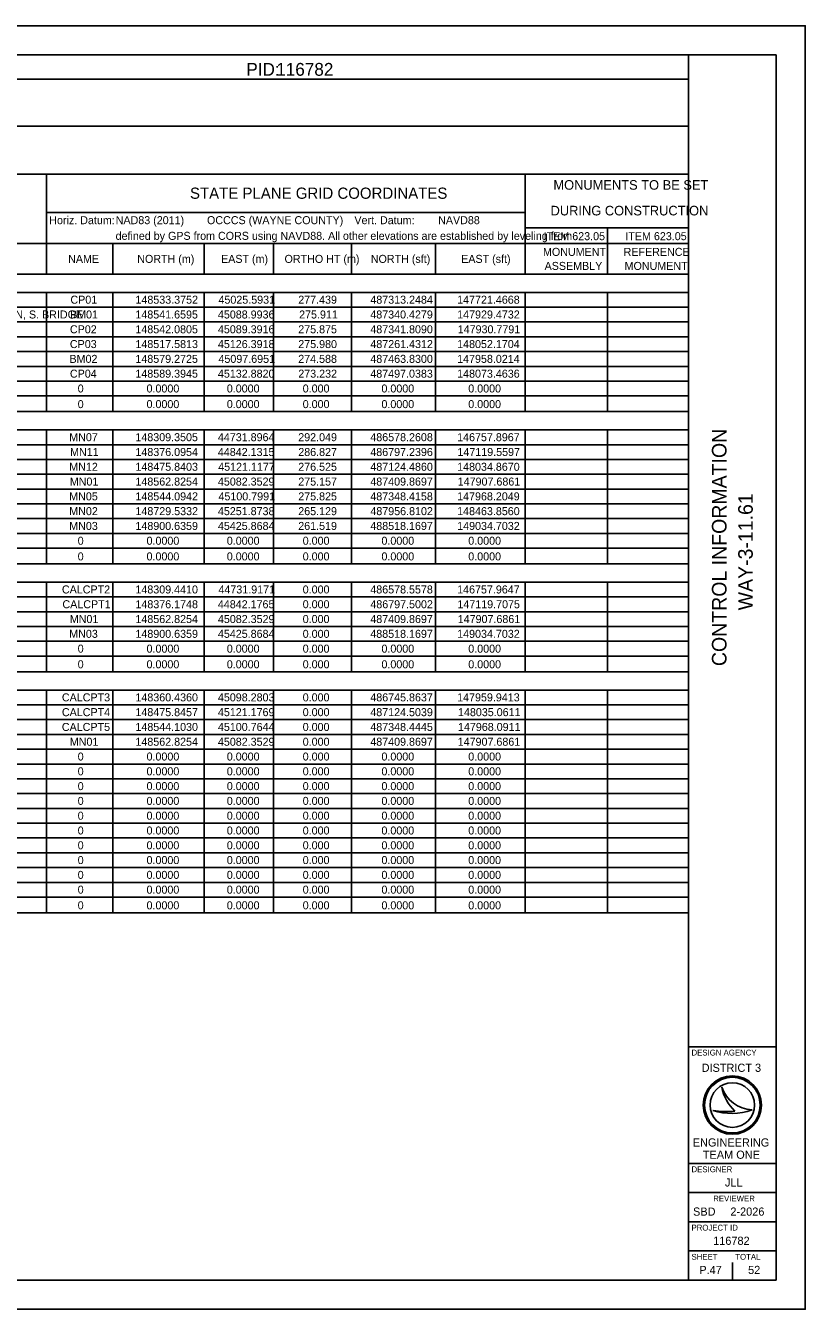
# Model space of a CAD drawing. Extents: x 0 to 680, y 0 to 440.
# Drawn here: x 412.9 to 680, y 0 to 440 of the extents above; entities that cross this region are included whole.
import ezdxf

# ---------------------------------------------------------------- set-up
doc = ezdxf.new("R2010")
doc.units = 0
for name, color, linetype in [('SH_Border', 7, 'Continuous'), ('SH_Cut_Line', 7, 'Continuous'), ('SH_Data', 7, 'Continuous')]:
    doc.layers.add(name, color=color, linetype=linetype)

msp = doc.modelspace()

# ---------------------------------------------------------------- linework, layer by layer
at = {"layer": 'SH_Border'}
for p, q in [((640, 10), (640, 430)), ((640, 90), (670, 90)), ((640, 50), (670, 50)), ((640, 40), (670, 40)), ((640, 30), (670, 30)), ((640, 20), (670, 20))]:
    msp.add_line(p, q, dxfattribs=at)
msp.add_lwpolyline([(30, 430), (670, 430), (670, 10), (30, 10)], close=True, dxfattribs=at)
at = {"layer": 'SH_Cut_Line'}
msp.add_lwpolyline([(0, 0), (680, 0), (680, 440), (0, 440)], close=True, dxfattribs=at)
at = {"layer": 'SH_Data'}
for p, q in [((30, 421.65), (640, 421.65)), ((640, 421.65), (640, 389.14)), ((259.49, 405.54), (640, 405.54)), ((259.49, 389.14), (640, 389.14)), ((419.99, 389.14), (419.99, 354.84)), ((584.05, 389.14), (584.05, 354.84)), ((640, 389.14), (640, 135.91)), ((419.99, 376.01), (584.05, 376.01)), ((584.05, 370.65), (640, 370.65)), ((612.26, 370.65), (612.26, 354.84)), ((30, 365.28), (640, 365.28)), ((442.75, 365.28), (442.75, 354.84)), ((474.05, 365.28), (474.05, 354.84)), ((497.75, 365.28), (497.75, 354.84)), ((524.54, 365.28), (524.54, 354.84)), ((553.23, 365.28), (553.23, 354.84)), ((30, 354.84), (640, 354.84)), ((30, 348.57), (640, 348.57)), ((419.99, 348.57), (419.99, 307.71)), ((442.75, 348.57), (442.75, 307.71)), ((474.05, 348.57), (474.05, 307.71)), ((497.75, 348.57), (497.75, 307.71)), ((524.54, 348.57), (524.54, 307.71)), ((553.23, 348.57), (553.23, 307.71)), ((584.05, 348.57), (584.05, 307.71)), ((612.26, 348.57), (612.26, 307.71)), ((30, 343.5), (640, 343.5)), ((30, 338.43), (640, 338.43)), ((30, 333.36), (640, 333.36)), ((30, 328.29), (640, 328.29)), ((30, 323.22), (640, 323.22)), ((30, 318.15), (640, 318.15)), ((30, 313.08), (640, 313.08)), ((30, 307.71), (640, 307.71)), ((30, 301.45), (640, 301.45)), ((419.99, 301.45), (419.99, 255.52)), ((442.75, 301.45), (442.75, 255.52)), ((474.05, 301.45), (474.05, 255.52)), ((497.75, 301.45), (497.75, 255.52)), ((524.54, 301.45), (524.54, 255.52)), ((553.23, 301.45), (553.23, 255.52)), ((584.05, 301.45), (584.05, 255.52)), ((612.26, 301.45), (612.26, 255.52)), ((30, 296.38), (640, 296.38)), ((30, 291.31), (640, 291.31)), ((30, 286.24), (640, 286.24)), ((30, 281.17), (640, 281.17)), ((30, 276.1), (640, 276.1)), ((30, 271.03), (640, 271.03)), ((30, 265.96), (640, 265.96)), ((30, 260.89), (640, 260.89)), ((30, 255.52), (640, 255.52)), ((30, 249.25), (640, 249.25)), ((419.99, 249.25), (419.99, 218.53)), ((442.75, 249.25), (442.75, 218.53)), ((474.05, 249.25), (474.05, 218.53)), ((497.75, 249.25), (497.75, 218.53)), ((524.54, 249.25), (524.54, 218.53)), ((553.23, 249.25), (553.23, 218.53)), ((584.05, 249.25), (584.05, 218.53)), ((612.26, 249.25), (612.26, 218.53)), ((30, 244.18), (640, 244.18)), ((30, 239.11), (640, 239.11)), ((30, 234.04), (640, 234.04)), ((30, 228.97), (640, 228.97)), ((30, 223.9), (640, 223.9)), ((30, 218.53), (640, 218.53)), ((30, 212.27), (640, 212.27)), ((419.99, 212.27), (419.99, 135.91)), ((442.75, 212.27), (442.75, 135.91)), ((474.05, 212.27), (474.05, 135.91)), ((497.75, 212.27), (497.75, 135.91)), ((524.54, 212.27), (524.54, 135.91)), ((553.23, 212.27), (553.23, 135.91)), ((584.05, 212.27), (584.05, 135.91)), ((612.26, 212.27), (612.26, 135.91)), ((30, 207.2), (640, 207.2)), ((30, 202.13), (640, 202.13)), ((30, 197.06), (640, 197.06)), ((30, 191.99), (640, 191.99)), ((30, 186.92), (640, 186.92)), ((30, 181.85), (640, 181.85)), ((30, 176.78), (640, 176.78)), ((30, 171.71), (640, 171.71)), ((30, 166.64), (640, 166.64)), ((30, 161.57), (640, 161.57)), ((30, 156.49), (640, 156.49)), ((30, 151.42), (640, 151.42)), ((30, 146.35), (640, 146.35)), ((30, 141.28), (640, 141.28)), ((30, 135.91), (640, 135.91)), ((651.35, 76.19), (651.35, 76.19)), ((648.34, 68.19), (648.34, 68.19)), ((655, 70), (655, 70)), ((661.75, 68.37), (661.75, 68.37)), ((647.5, 13.5), (647.5, 13.5)), ((655, 10), (655, 16))]:
    msp.add_line(p, q, dxfattribs=at)
for radius in [10, 9.54, 9.54, 7.64]:
    msp.add_circle((655, 70), radius, dxfattribs=at)
for centre, radius, start, end in [((662.32, 79.95), 11.6, 198.9257, 198.9319), ((666.93, 79.4), 15.91, 191.6379, 191.6421), ((662.32, 79.95), 11.6, 198.9319, 267.1657), ((666.93, 79.4), 15.91, 191.6421, 226.0947), ((654.79, 87.4), 20.26, 251.4576, 290.0832), ((652.96, 93.09), 25.32, 259.4964, 259.4995), ((654.79, 87.4), 20.26, 251.4527, 251.4576), ((652.96, 93.09), 25.32, 259.4995, 276.6672)]:
    msp.add_arc(centre, radius, start, end, dxfattribs=at)

# ---------------------------------------------------------------- texts
for s, height, p in [('PID:', 4.39, (488.46, 422.84)), ('116782', 4.39, (498.7, 422.84)), ('STATE PLANE GRID COORDINATES', 3.8416, (469.15, 380.66)), ('  MONUMENTS TO BE SET', 3.2928, (591.24, 383.77)), ('Horiz. Datum:', 2.744, (420.94, 371.96)), ('NAD83 (2011)', 2.744, (443.7, 371.96)), ('OCCCS (WAYNE COUNTY)', 2.744, (474.99, 371.96)), ('Vert. Datum:', 2.744, (525.49, 371.96)), ('NAVD88', 2.744, (554.18, 371.96)), (' DURING CONSTRUCTION', 3.2928, (591.49, 374.96)), (' defined by GPS from CORS using NAVD88. All other elevations are established by leveling from .', 2.744, (442.65, 366.59)), ('ITEM 623.05', 2.744, (590.36, 366.47)), ('ITEM 623.05', 2.744, (618.34, 366.47)), ('NAME', 2.744, (427.4, 358.69)), ('NORTH (m)', 2.744, (451.08, 358.69)), ('EAST (m)', 2.744, (479.8, 358.69)), ('ORTHO HT (m)', 2.744, (501.55, 358.69)), ('NORTH (sft)', 2.744, (531.11, 358.69)), ('EAST (sft)', 2.744, (562.08, 358.69)), ('MONUMENT ', 2.744, (590.11, 361.09)), ('REFERENCE ', 2.744, (617.74, 361.09)), ('ASSEMBLY', 2.744, (590.66, 356.28)), ('MONUMENT', 2.744, (618.08, 356.28)), ('CP01', 2.744, (428.19, 344.7)), ('148533.3752', 2.744, (450.47, 344.7)), ('45025.5931', 2.744, (478.91, 344.7)), ('277.439', 2.744, (506.25, 344.7)), ('487313.2484', 2.744, (530.95, 344.7)), ('147721.4668', 2.744, (560.7, 344.7)), ('SMSS IN GD RAIL POST CENTER MEDIAN ON CURL N. INTERSECTION, S. BRIDGE', 2.744, (288.18, 339.63)), ('BM01', 2.744, (428.04, 339.63)), ('148541.6595', 2.744, (450.45, 339.63)), ('45088.9936', 2.744, (478.72, 339.63)), ('275.911', 2.744, (506.55, 339.63)), ('487340.4279', 2.744, (530.94, 339.63)), ('147929.4732', 2.744, (560.71, 339.63)), ('CP02', 2.744, (428.01, 334.56)), ('148542.0805', 2.744, (450.45, 334.56)), ('45089.3916', 2.744, (478.72, 334.56)), ('275.875', 2.744, (506.25, 334.56)), ('487341.8090', 2.744, (530.95, 334.56)), ('147930.7791', 2.744, (560.89, 334.56)), ('CP03', 2.744, (428, 329.49)), ('148517.5813', 2.744, (450.46, 329.49)), ('45126.3918', 2.744, (478.72, 329.49)), ('275.980', 2.744, (506.26, 329.49)), ('487261.4312', 2.744, (530.96, 329.49)), ('148052.1704', 2.744, (560.7, 329.49)), ('BM02', 2.744, (427.86, 324.42)), ('148579.2725', 2.744, (450.45, 324.42)), ('45097.6951', 2.744, (478.91, 324.42)), ('274.588', 2.744, (506.25, 324.42)), ('487463.8300', 2.744, (530.95, 324.42)), ('147958.0214', 2.744, (560.7, 324.42)), ('CP04', 2.744, (428.01, 319.35)), ('148589.3945', 2.744, (450.45, 319.35)), ('45132.8820', 2.744, (478.72, 319.35)), ('273.232', 2.744, (506.27, 319.35)), ('487497.0383', 2.744, (530.94, 319.35)), ('148073.4636', 2.744, (560.7, 319.35)), ('0', 2.74, (430.68, 314.27)), ('0.0000', 2.744, (454.27, 314.27)), ('0.0000', 2.744, (481.77, 314.27)), ('0.000', 2.744, (507.78, 314.27)), ('0.0000', 2.744, (534.76, 314.27)), ('0.0000', 2.744, (564.51, 314.27)), ('0', 2.74, (430.68, 308.91)), ('0.0000', 2.744, (454.27, 308.91)), ('0.0000', 2.744, (481.77, 308.91)), ('0.000', 2.744, (507.78, 308.91)), ('0.0000', 2.744, (534.76, 308.91)), ('0.0000', 2.744, (564.51, 308.91)), ('MN07', 2.744, (427.78, 297.57)), ('148309.3505', 2.744, (450.45, 297.57)), ('44731.8964', 2.744, (478.72, 297.57)), ('292.049', 2.744, (506.25, 297.57)), ('486578.2608', 2.744, (530.94, 297.57)), ('146757.8967', 2.744, (560.7, 297.57)), ('MN11', 2.744, (428.07, 292.5)), ('148376.0954', 2.744, (450.46, 292.5)), ('44842.1315', 2.744, (478.71, 292.5)), ('286.827', 2.744, (506.26, 292.5)), ('486797.2396', 2.744, (530.94, 292.5)), ('147119.5597', 2.744, (560.8, 292.5)), ('MN12', 2.744, (427.79, 287.43)), ('148475.8403', 2.744, (450.46, 287.43)), ('45121.1177', 2.744, (478.82, 287.43)), ('276.525', 2.744, (506.25, 287.43)), ('487124.4860', 2.744, (530.95, 287.43)), ('148034.8670', 2.744, (560.7, 287.43)), ('MN01', 2.744, (427.97, 282.36)), ('148562.8254', 2.744, (450.46, 282.36)), ('45082.3529', 2.744, (478.72, 282.36)), ('275.157', 2.744, (506.26, 282.36)), ('487409.8697', 2.744, (530.94, 282.36)), ('147907.6861', 2.744, (560.89, 282.36)), ('MN05', 2.744, (427.77, 277.29)), ('148544.0942', 2.744, (450.47, 277.29)), ('45100.7991', 2.744, (478.91, 277.29)), ('275.825', 2.744, (506.25, 277.29)), ('487348.4158', 2.744, (530.94, 277.29)), ('147968.2049', 2.744, (560.7, 277.29)), ('MN02', 2.744, (427.79, 272.22)), ('148729.5332', 2.744, (450.47, 272.22)), ('45251.8738', 2.744, (478.72, 272.22)), ('265.129', 2.744, (506.25, 272.22)), ('487956.8102', 2.744, (530.96, 272.22)), ('148463.8560', 2.744, (560.7, 272.22)), ('MN03', 2.744, (427.78, 267.15)), ('148900.6359', 2.744, (450.46, 267.15)), ('45425.8684', 2.744, (478.72, 267.15)), ('261.519', 2.744, (506.25, 267.15)), ('488518.1697', 2.744, (530.94, 267.15)), ('149034.7032', 2.744, (560.71, 267.15)), ('0', 2.74, (430.68, 262.08)), ('0.0000', 2.744, (454.27, 262.08)), ('0.0000', 2.744, (481.77, 262.08)), ('0.000', 2.744, (507.78, 262.08)), ('0.0000', 2.744, (534.76, 262.08)), ('0.0000', 2.744, (564.51, 262.08)), ('0', 2.74, (430.68, 256.71)), ('0.0000', 2.744, (454.27, 256.71)), ('0.0000', 2.744, (481.77, 256.71)), ('0.000', 2.744, (507.78, 256.71)), ('0.0000', 2.744, (534.76, 256.71)), ('0.0000', 2.744, (564.51, 256.71)), ('CALCPT2', 2.744, (425.27, 245.38)), ('148309.4410', 2.744, (450.46, 245.38)), ('44731.9171', 2.744, (478.91, 245.38)), ('0.000', 2.744, (507.78, 245.38)), ('486578.5578', 2.744, (530.94, 245.38)), ('146757.9647', 2.744, (560.7, 245.38)), ('CALCPT1', 2.744, (425.45, 240.31)), ('148376.1748', 2.744, (450.46, 240.31)), ('44842.1765', 2.744, (478.71, 240.31)), ('0.000', 2.744, (507.78, 240.31)), ('486797.5002', 2.744, (530.96, 240.31)), ('147119.7075', 2.744, (560.79, 240.31)), ('MN01', 2.744, (427.97, 235.24)), ('148562.8254', 2.744, (450.46, 235.24)), ('45082.3529', 2.744, (478.72, 235.24)), ('0.000', 2.744, (507.78, 235.24)), ('487409.8697', 2.744, (530.94, 235.24)), ('147907.6861', 2.744, (560.89, 235.24)), ('MN03', 2.744, (427.78, 230.17)), ('148900.6359', 2.744, (450.46, 230.17)), ('45425.8684', 2.744, (478.72, 230.17)), ('0.000', 2.744, (507.78, 230.17)), ('488518.1697', 2.744, (530.94, 230.17)), ('149034.7032', 2.744, (560.71, 230.17)), ('0', 2.74, (430.68, 225.09)), ('0.0000', 2.744, (454.27, 225.09)), ('0.0000', 2.744, (481.77, 225.09)), ('0.000', 2.744, (507.78, 225.09)), ('0.0000', 2.744, (534.76, 225.09)), ('0.0000', 2.744, (564.51, 225.09)), ('0', 2.74, (430.68, 219.73)), ('0.0000', 2.744, (454.27, 219.73)), ('0.0000', 2.744, (481.77, 219.73)), ('0.000', 2.744, (507.78, 219.73)), ('0.0000', 2.744, (534.76, 219.73)), ('0.0000', 2.744, (564.51, 219.73)), ('CALCPT3', 2.744, (425.26, 208.39)), ('148360.4360', 2.744, (450.46, 208.39)), ('45098.2803', 2.744, (478.72, 208.39)), ('0.000', 2.744, (507.78, 208.39)), ('486745.8637', 2.744, (530.94, 208.39)), ('147959.9413', 2.744, (560.7, 208.39)), ('CALCPT4', 2.744, (425.27, 203.32)), ('148475.8457', 2.744, (450.46, 203.32)), ('45121.1769', 2.744, (478.72, 203.32)), ('0.000', 2.744, (507.78, 203.32)), ('487124.5039', 2.744, (530.94, 203.32)), ('148035.0611', 2.744, (560.99, 203.32)), ('CALCPT5', 2.744, (425.25, 198.25)), ('148544.1030', 2.744, (450.46, 198.25)), ('45100.7644', 2.744, (478.72, 198.25)), ('0.000', 2.744, (507.78, 198.25)), ('487348.4445', 2.744, (530.94, 198.25)), ('147968.0911', 2.744, (560.99, 198.25)), ('MN01', 2.744, (427.97, 193.18)), ('148562.8254', 2.744, (450.46, 193.18)), ('45082.3529', 2.744, (478.72, 193.18)), ('0.000', 2.744, (507.78, 193.18)), ('487409.8697', 2.744, (530.94, 193.18)), ('147907.6861', 2.744, (560.89, 193.18)), ('0', 2.74, (430.68, 188.11)), ('0.0000', 2.744, (454.27, 188.11)), ('0.0000', 2.744, (481.77, 188.11)), ('0.000', 2.744, (507.78, 188.11)), ('0.0000', 2.744, (534.76, 188.11)), ('0.0000', 2.744, (564.51, 188.11)), ('0', 2.74, (430.68, 183.04)), ('0.0000', 2.744, (454.27, 183.04)), ('0.0000', 2.744, (481.77, 183.04)), ('0.000', 2.744, (507.78, 183.04)), ('0.0000', 2.744, (534.76, 183.04)), ('0.0000', 2.744, (564.51, 183.04)), ('0', 2.74, (430.68, 177.97)), ('0.0000', 2.744, (454.27, 177.97)), ('0.0000', 2.744, (481.77, 177.97)), ('0.000', 2.744, (507.78, 177.97)), ('0.0000', 2.744, (534.76, 177.97)), ('0.0000', 2.744, (564.51, 177.97)), ('0', 2.74, (430.68, 172.9)), ('0.0000', 2.744, (454.27, 172.9)), ('0.0000', 2.744, (481.77, 172.9)), ('0.000', 2.744, (507.78, 172.9)), ('0.0000', 2.744, (534.76, 172.9)), ('0.0000', 2.744, (564.51, 172.9)), ('0', 2.74, (430.68, 167.83)), ('0.0000', 2.744, (454.27, 167.83)), ('0.0000', 2.744, (481.77, 167.83)), ('0.000', 2.744, (507.78, 167.83)), ('0.0000', 2.744, (534.76, 167.83)), ('0.0000', 2.744, (564.51, 167.83)), ('0', 2.74, (430.68, 162.76)), ('0.0000', 2.744, (454.27, 162.76)), ('0.0000', 2.744, (481.77, 162.76)), ('0.000', 2.744, (507.78, 162.76)), ('0.0000', 2.744, (534.76, 162.76)), ('0.0000', 2.744, (564.51, 162.76)), ('0', 2.74, (430.68, 157.69)), ('0.0000', 2.744, (454.27, 157.69)), ('0.0000', 2.744, (481.77, 157.69)), ('0.000', 2.744, (507.78, 157.69)), ('0.0000', 2.744, (534.76, 157.69)), ('0.0000', 2.744, (564.51, 157.69)), ('0', 2.74, (430.68, 152.62)), ('0.0000', 2.744, (454.27, 152.62)), ('0.0000', 2.744, (481.77, 152.62)), ('0.000', 2.744, (507.78, 152.62)), ('0.0000', 2.744, (534.76, 152.62)), ('0.0000', 2.744, (564.51, 152.62)), ('0', 2.74, (430.68, 147.55)), ('0.0000', 2.744, (454.27, 147.55)), ('0.0000', 2.744, (481.77, 147.55)), ('0.000', 2.744, (507.78, 147.55)), ('0.0000', 2.744, (534.76, 147.55)), ('0.0000', 2.744, (564.51, 147.55)), ('0', 2.74, (430.68, 142.48)), ('0.0000', 2.744, (454.27, 142.48)), ('0.0000', 2.744, (481.77, 142.48)), ('0.000', 2.744, (507.78, 142.48)), ('0.0000', 2.744, (534.76, 142.48)), ('0.0000', 2.744, (564.51, 142.48)), ('0', 2.74, (430.68, 137.11)), ('0.0000', 2.744, (454.27, 137.11)), ('0.0000', 2.744, (481.77, 137.11)), ('0.000', 2.744, (507.78, 137.11)), ('0.0000', 2.744, (534.76, 137.11)), ('0.0000', 2.744, (564.51, 137.11)), ('DESIGN AGENCY', 2, (641, 87)), ('DISTRICT 3', 2.8, (644.47, 81.4)), ('ENGINEERING', 2.8, (641.43, 55.8)), ('TEAM ONE', 2.8, (644.89, 51.6)), ('DESIGNER', 2, (641, 47)), ('JLL', 2.8, (652.46, 42.1)), ('REVIEWER', 2, (648.44, 37)), ('SBD', 2.8, (641.53, 32.1)), ('2-2026', 2.8, (654.32, 32.1)), ('PROJECT ID', 2, (641, 27)), ('116782', 2.8, (648.42, 22.1)), ('SHEET', 2, (641, 17)), ('TOTAL', 2, (656, 17)), ('P.47', 2.8, (643.67, 12.1)), ('52', 2.8, (660.39, 12.1))]:
    msp.add_text(s, height=height, dxfattribs=at).set_placement(p)
for s, p in [('CONTROL INFORMATION', (653, 220.48)), ('WAY-3-11.61', (662, 239.59))]:
    msp.add_text(s, height=5, rotation=90, dxfattribs=at).set_placement(p)

doc.saveas('drawing.dxf')
